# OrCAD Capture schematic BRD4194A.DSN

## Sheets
1 03: I/O Port Connections: size A3; title: EFR32xG27 2.4 GHz 8 dBm Radio Board; rev: A04; company: Silicon Labs; note: BRD4194A
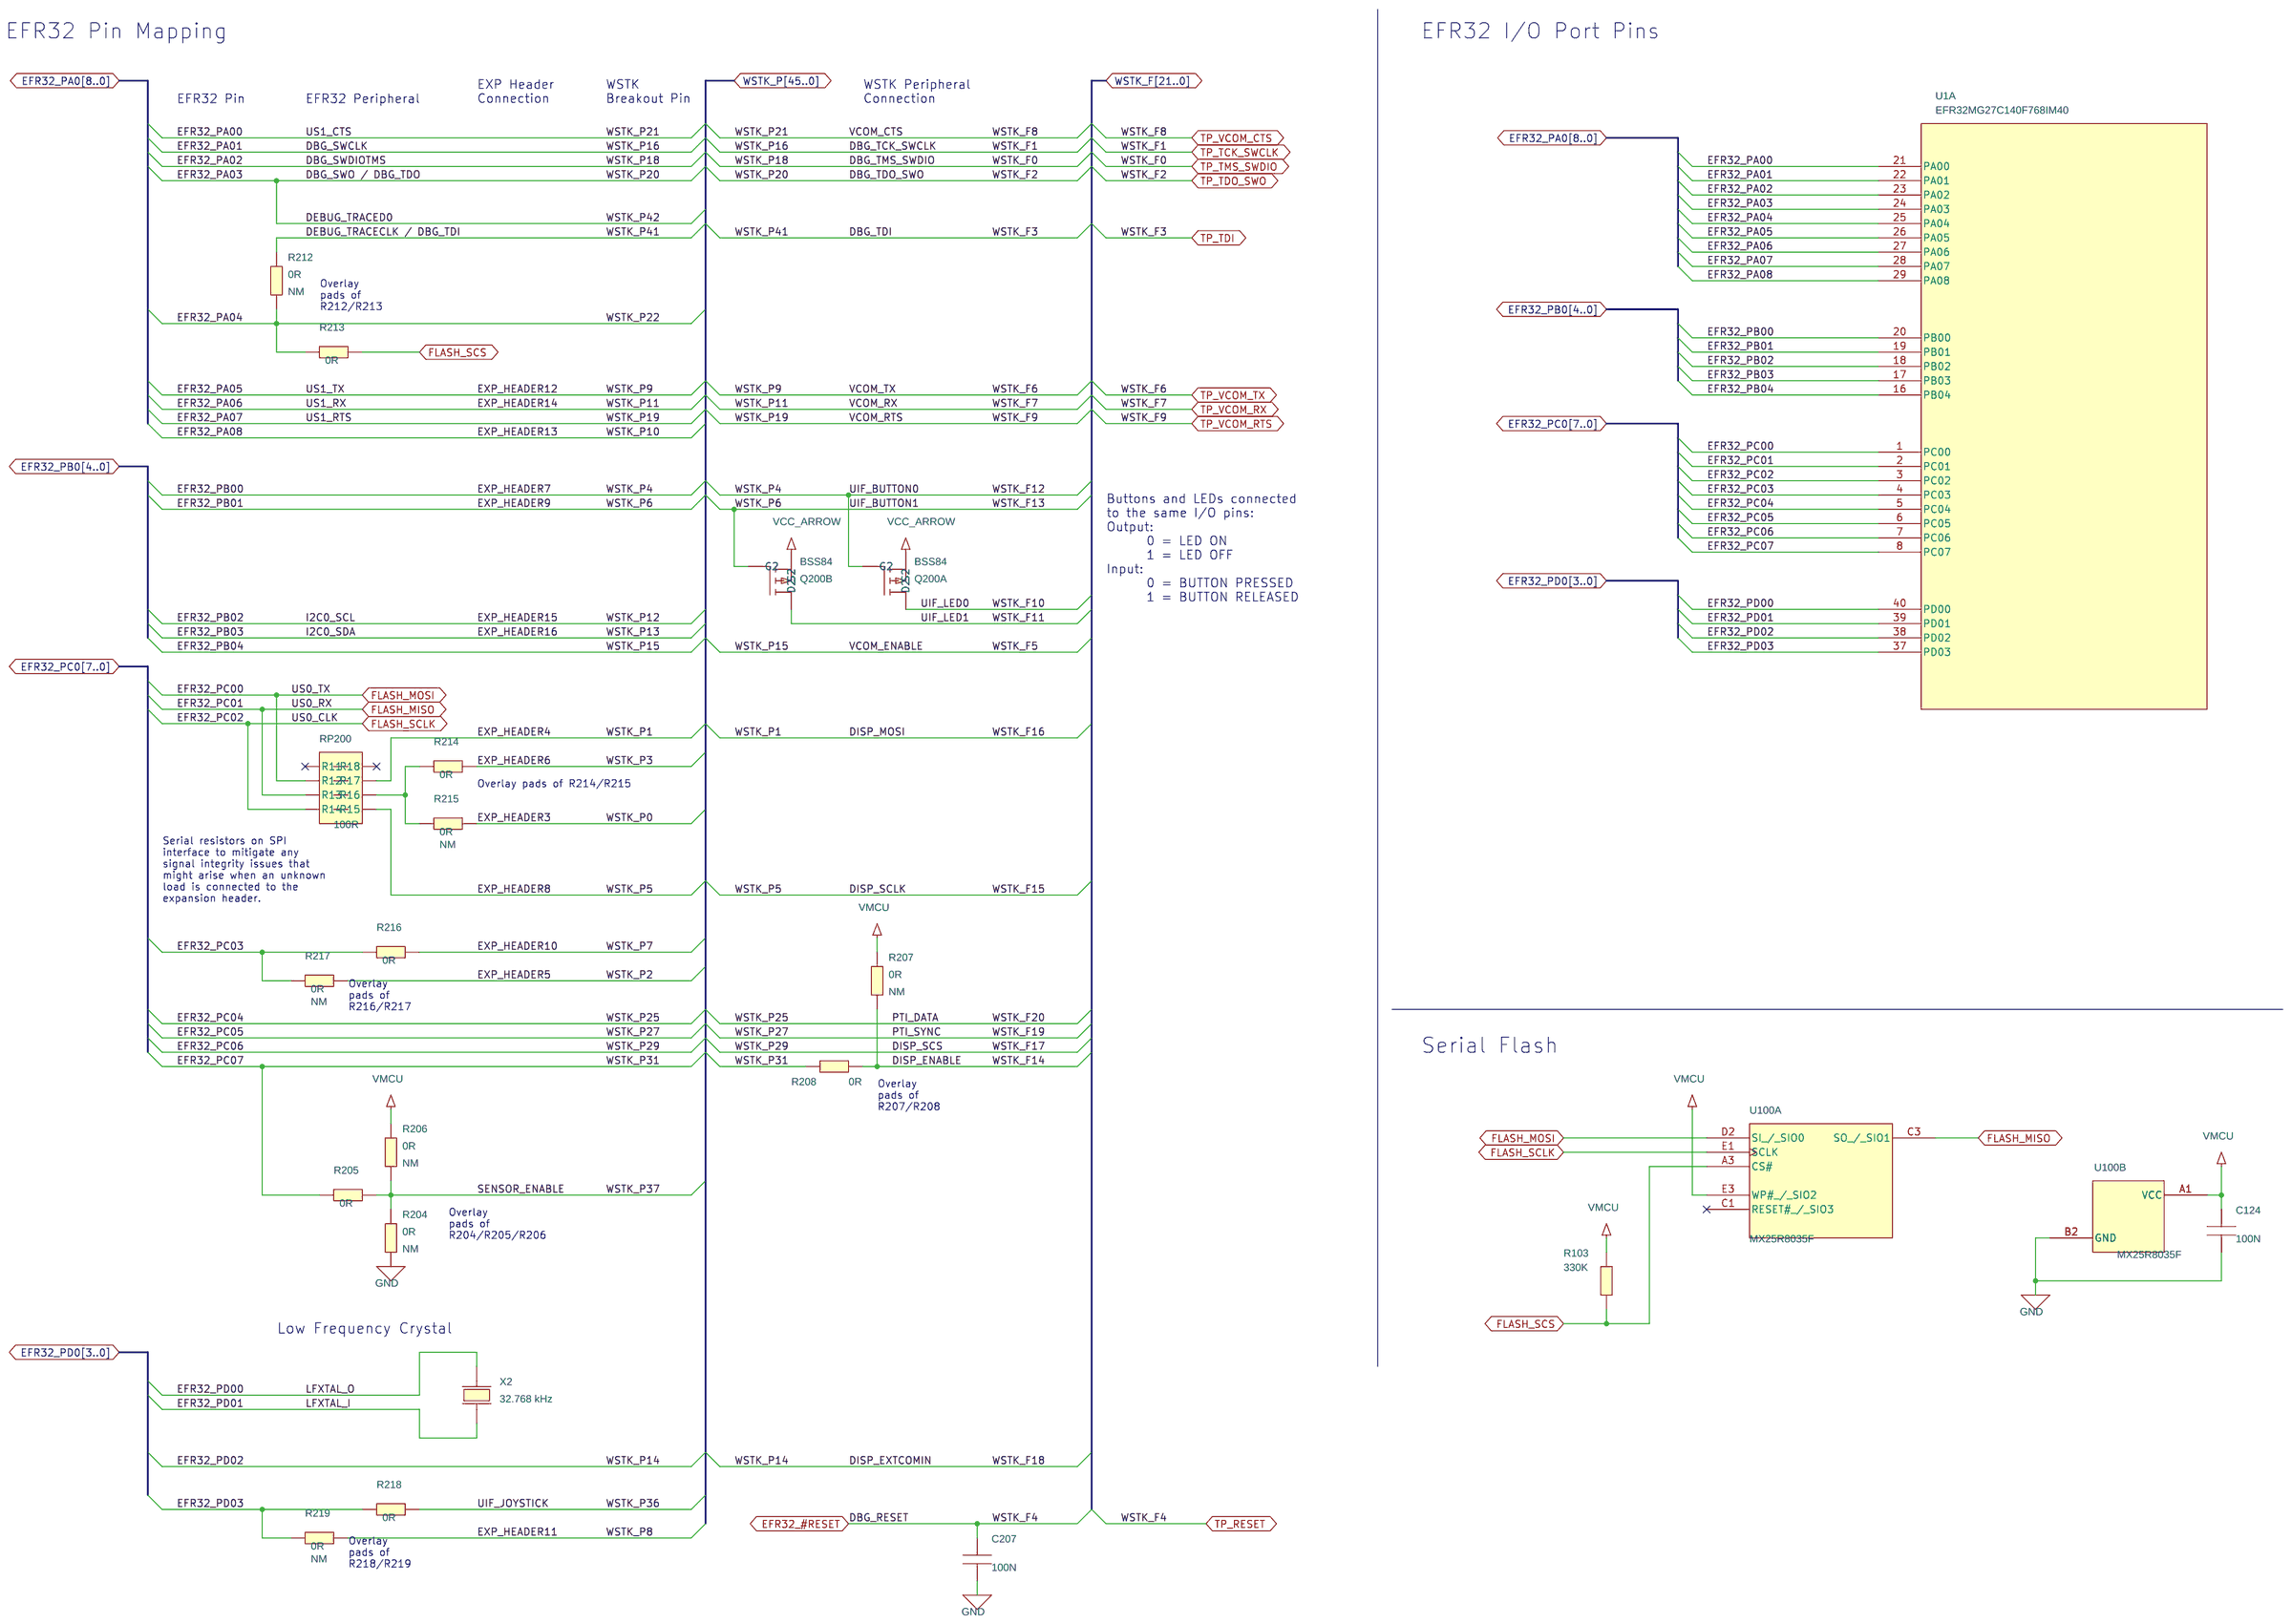
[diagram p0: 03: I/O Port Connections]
2 01: Title Page
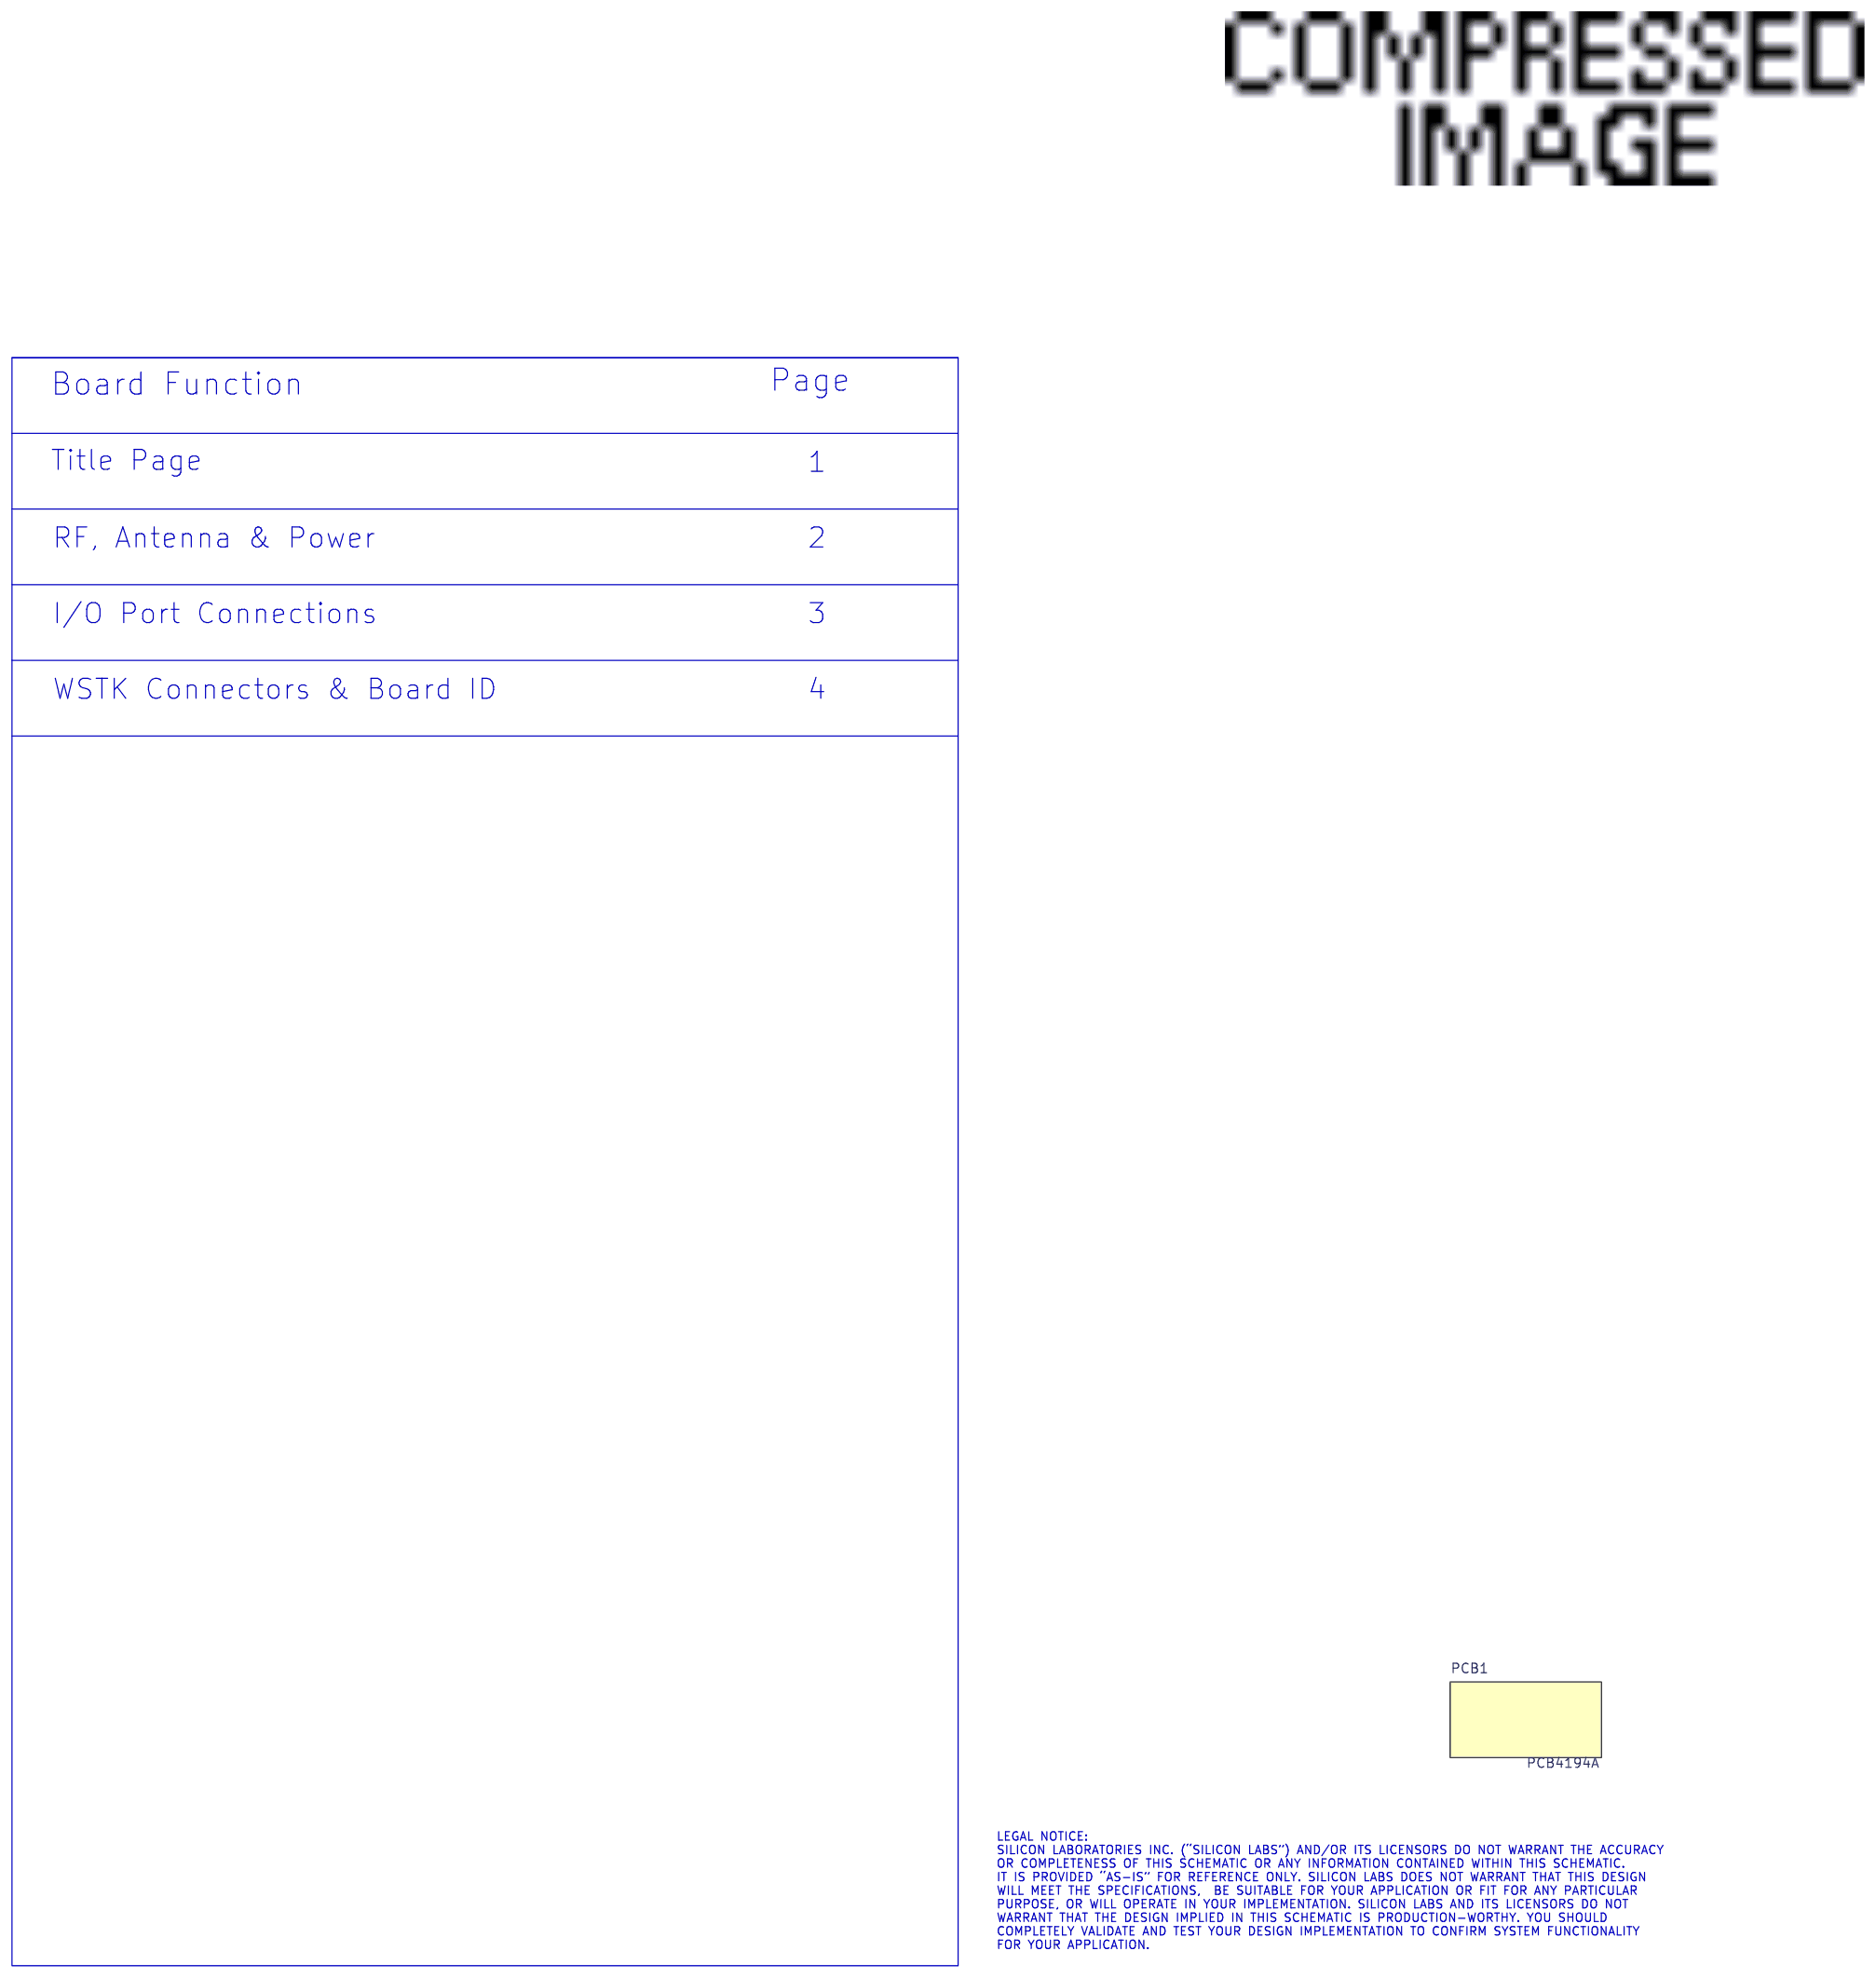
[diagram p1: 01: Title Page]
3 02: RF, Antenna and Power: size A3
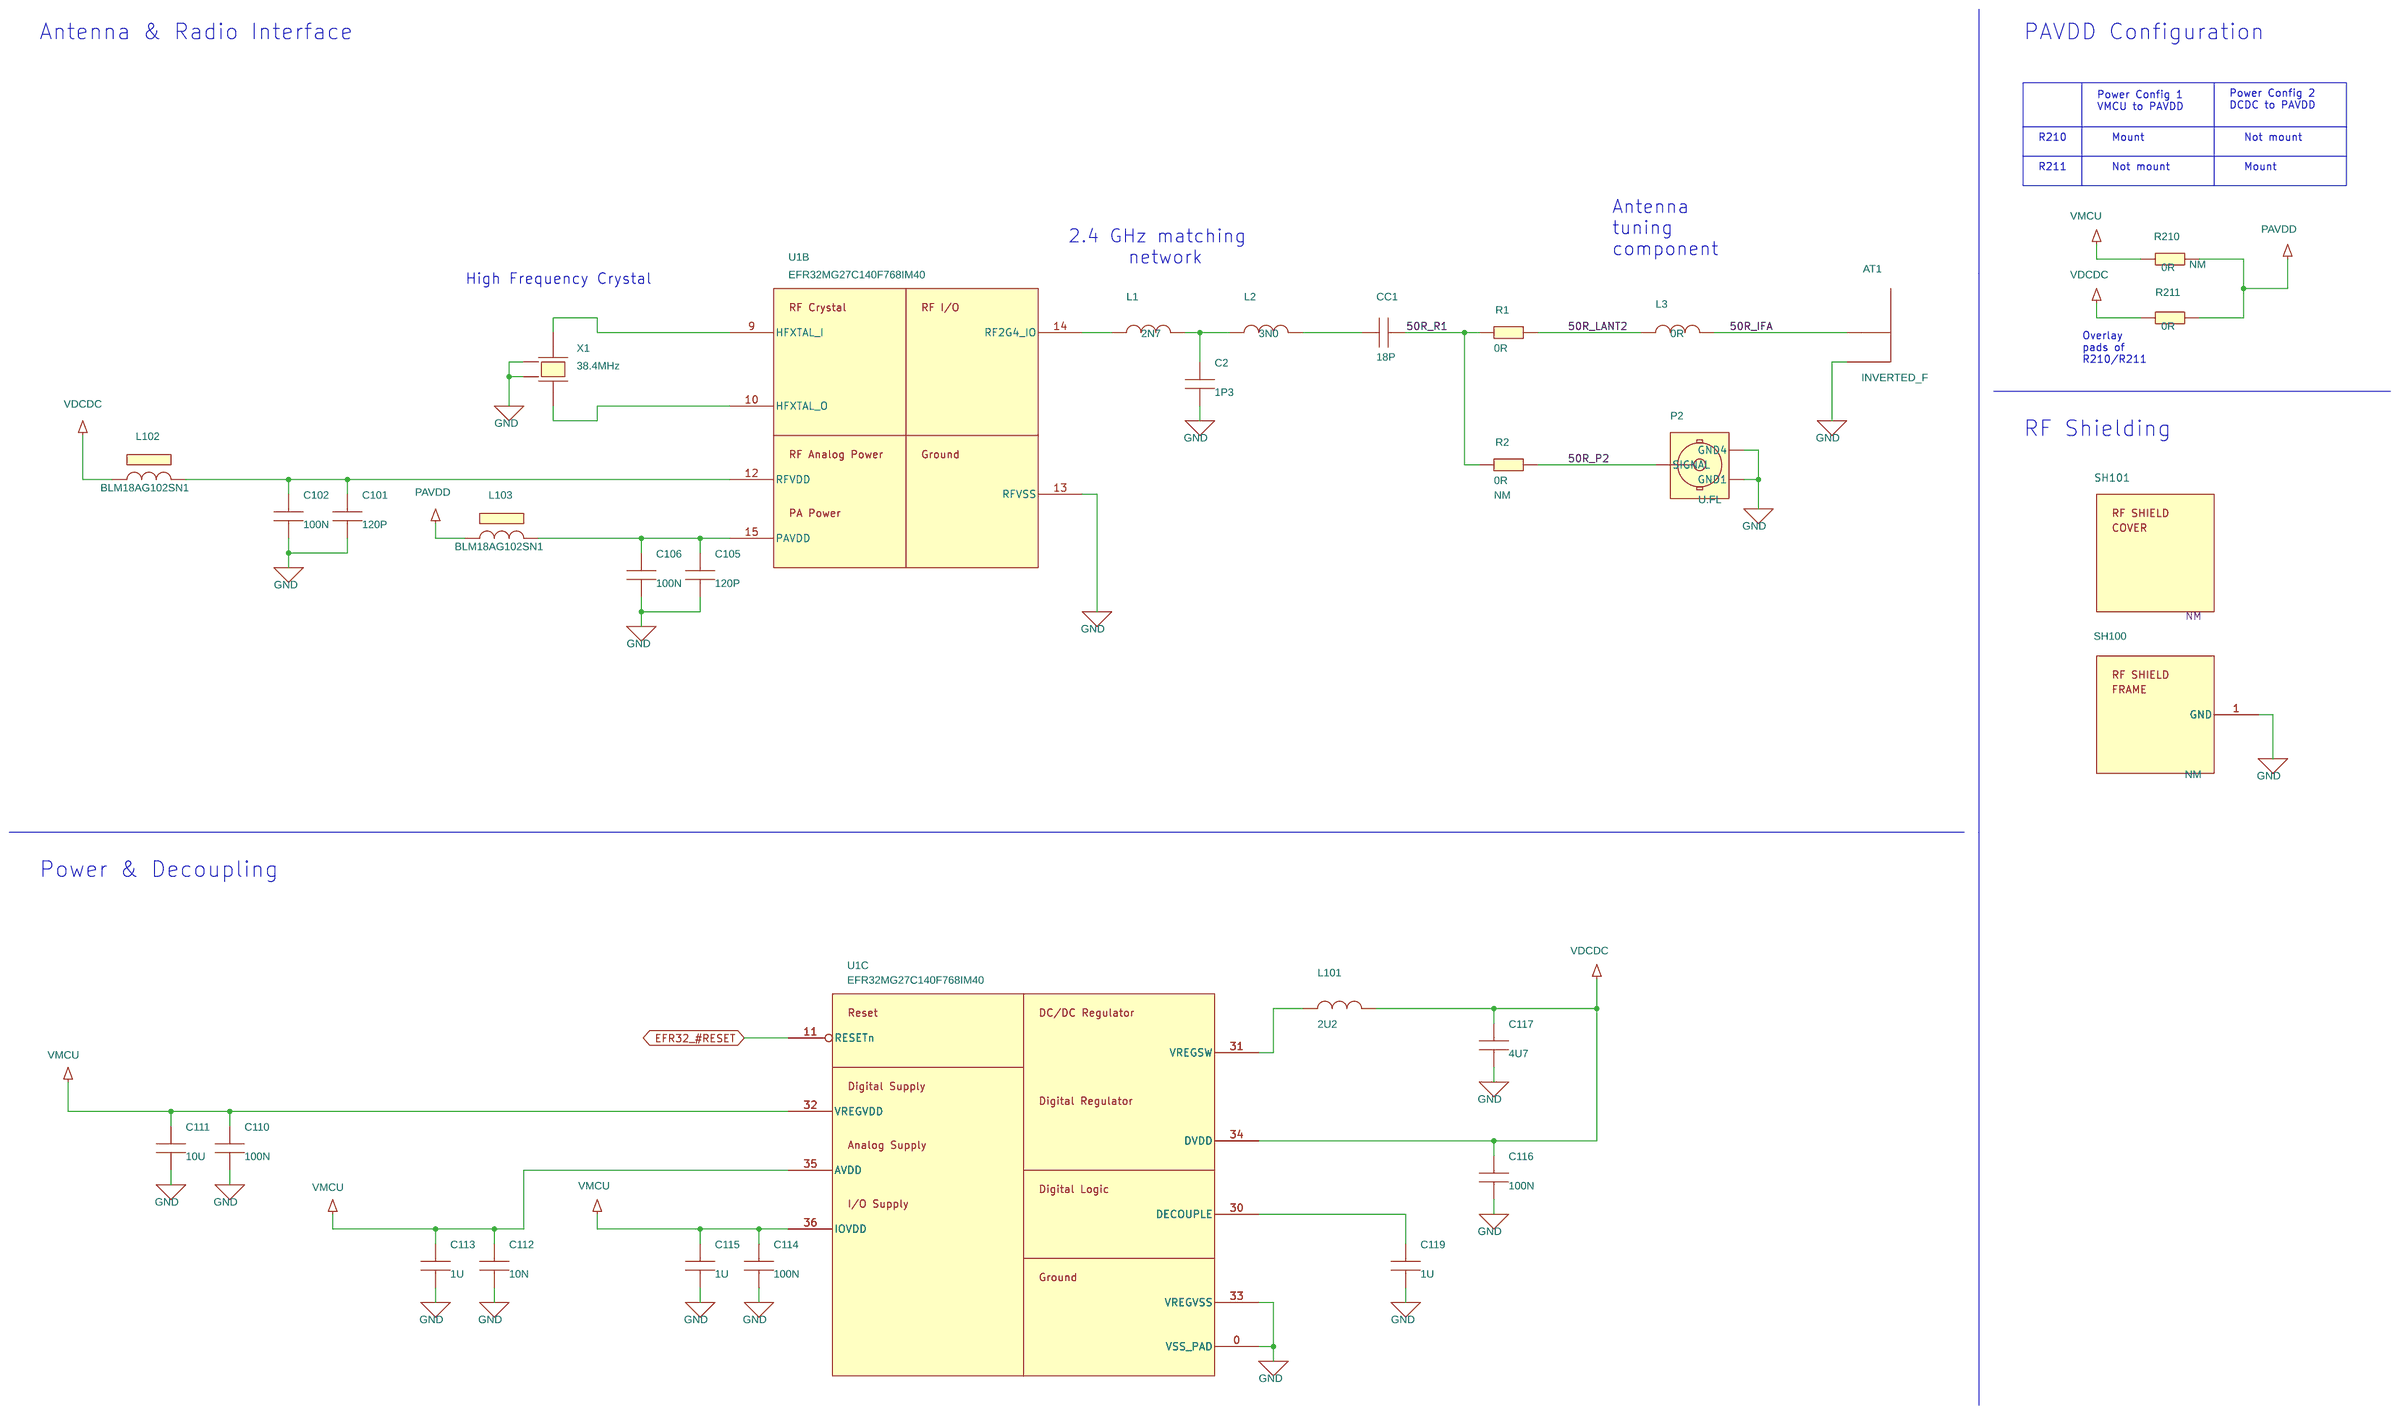
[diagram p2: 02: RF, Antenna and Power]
4 04: WSTK Connectors & Board ID: size A3
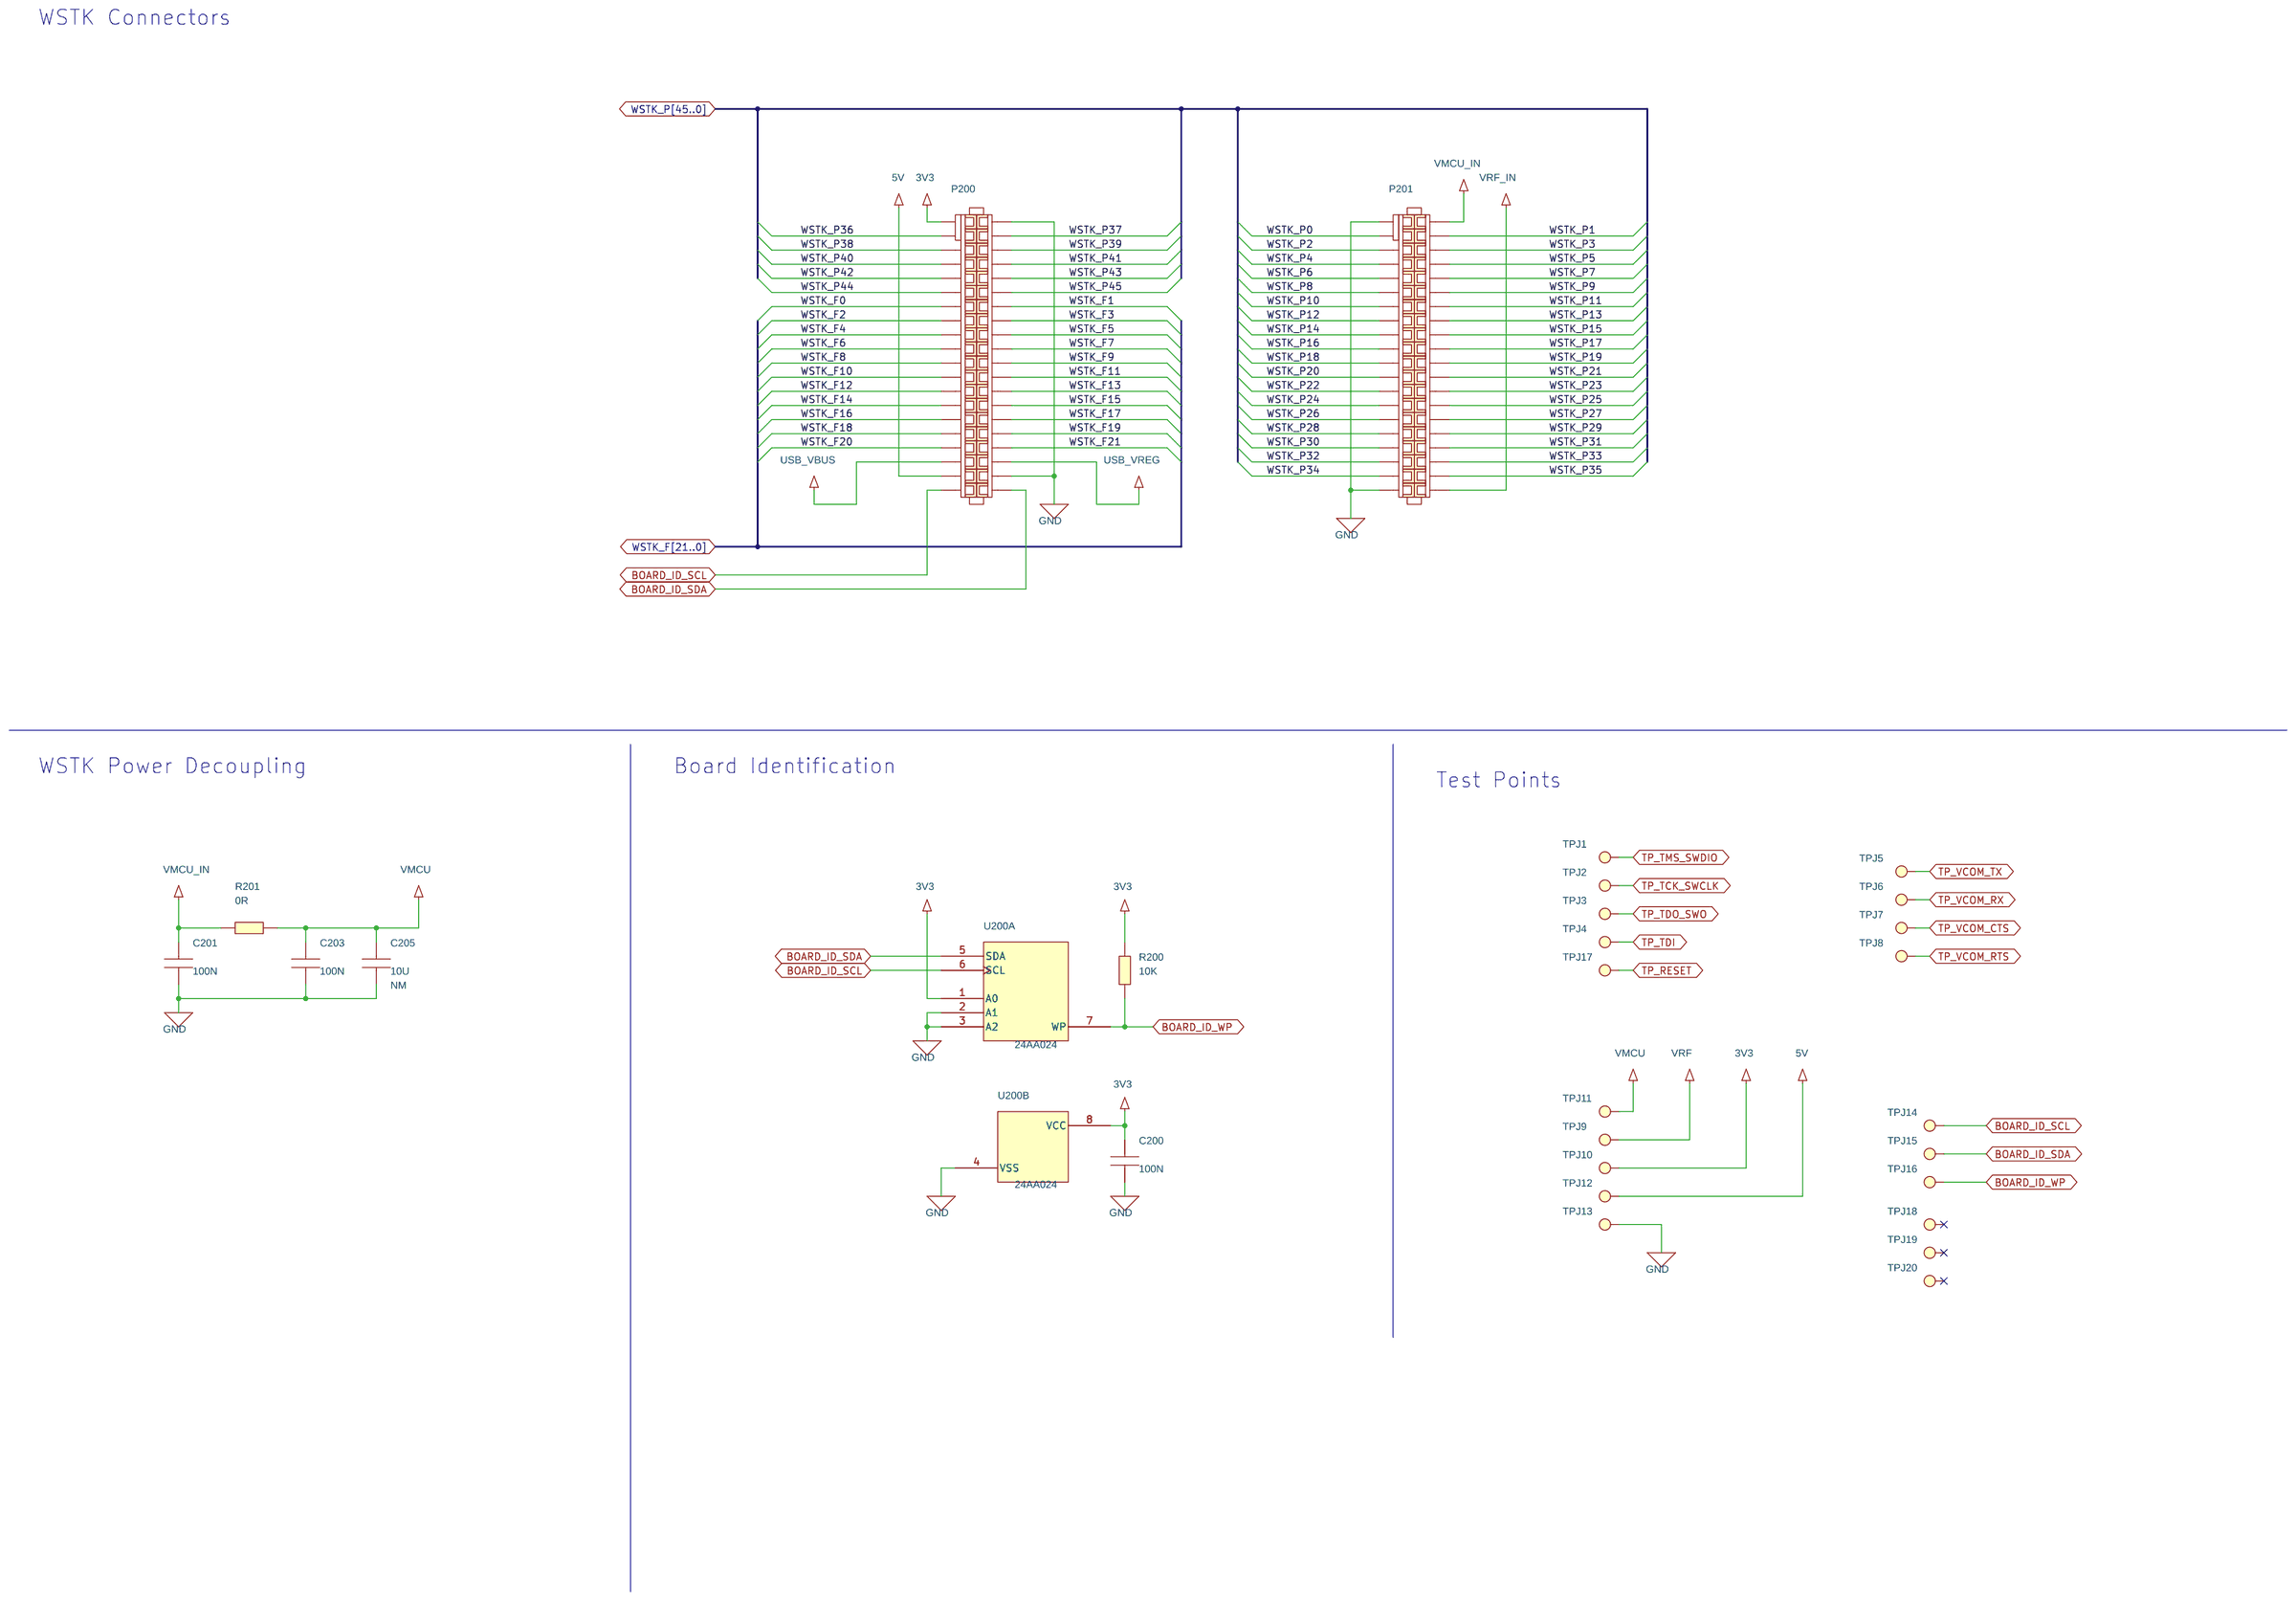
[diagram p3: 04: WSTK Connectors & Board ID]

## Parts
sheet 01: Title Page
PCB1  PCB4194A  [N/A]
sheet 02: RF, Antenna and Power
AT1  INVERTED_F  [EM358x_INVERTED_F]
C2  1P3  [C0201_L]
C101  120P  [C0201_L]
C102  100N  [C0201_L]
C105  120P  [C0201_L]
C106  100N  [C0201_L]
C110  100N  [C0201_L]
C111  10U  [C0603_L]
C112  10N  [C0201_L]
C113  1U  [C0402_L]
C114  100N  [C0201_L]
C115  1U  [C0402_L]
C116  100N  [C0201_L]
C117  4U7  [C0603_L]
C119  1U  [C0201_L]
CC1  18P  [C0201_L]
L1  2N7  [COIL_0201_L]
L2  3N0  [COIL_0201_L]
L3  0R  [COIL_0402_L]
L101  2U2  [COIL_1008_L]
L102  BLM18AG102SN1  [COIL_MUR_BLM18_0603]
L103  BLM18AG102SN1  [COIL_MUR_BLM18_0603]
P2  U.FL  [COAX_HIROSE_U.FL_CL331-0471]
R1  0R  [R0402_L]
R2  0R  [R0402_L]
R210  0R  [R0402_L]
R211  0R  [R0402_L]
SH100  RF_SHIELD_FRAME_BMI-S-202-F  [Laird_BMI-S-202-F]
SH101  RF_SHIELD_COVER_BMI-S-202-C
U1  EFR32MG27C140F768IM40  [QFN40_M040_5.0X5.0_EP_RP_SL]  (sections A,B,C)
X1  38.4MHz  [KDS_DSX211SH_2016]
sheet 03: I/O Port Connections
C124  100N  [C0201_L]
C207  100N  [C0201_L]
Q200  BSS84  [SOT-363]  (sections A,B)
R103  330K  [R0201_L]
R204  0R  [R0402_L]
R205  0R  [R0402_L]
R206  0R  [R0402_L]
R207  0R  [R0402_L]
R208  0R  [R0402_L]
R212  0R  [R0402_L]
R213  0R  [R0402_L]
R214  0R  [R0402_L]
R215  0R  [R0402_L]
R216  0R  [R0402_L]
R217  0R  [R0402_L]
R218  0R  [R0402_L]
R219  0R  [R0402_L]
RP200  100R  [RES_MNR04-8]
U100  MX25R8035F  [BGA8_M040_1.24x1.75_WLCSP]  (sections A,B)
X2  32.768 kHz  [X_MCS_CM8V-T1A]
sheet 04: WSTK Connectors & Board ID
C200  100N  [C0201_L]
C201  100N  [C0201_L]
C203  100N  [C0201_L]
C205  10U  [C0805_L]
P200  SOCKET_WCON_2X20_1.27MM_SMD  [SAM_SFC-120-T2-D-A-2X20_SNUM]
P201  SOCKET_WCON_2X20_1.27MM_SMD  [SAM_SFC-120-T2-D-A-2X20_SNUM]
R200  10K  [R0201_L]
R201  0R  [R0402_L]
TPJ1  TPJ_SMD  [TP_1.0_SMD]
TPJ2  TPJ_SMD  [TP_1.0_SMD]
TPJ3  TPJ_SMD  [TP_1.0_SMD]
TPJ4  TPJ_SMD  [TP_1.0_SMD]
TPJ5  TPJ_SMD  [TP_1.0_SMD]
TPJ6  TPJ_SMD  [TP_1.0_SMD]
TPJ7  TPJ_SMD  [TP_1.0_SMD]
TPJ8  TPJ_SMD  [TP_1.0_SMD]
TPJ9  TPJ_SMD  [TP_1.0_SMD]
TPJ10  TPJ_SMD  [TP_1.0_SMD]
TPJ11  TPJ_SMD  [TP_1.0_SMD]
TPJ12  TPJ_SMD  [TP_1.0_SMD]
TPJ13  TPJ_SMD  [TP_1.0_SMD]
TPJ14  TPJ_SMD  [TP_1.0_SMD]
TPJ15  TPJ_SMD  [TP_1.0_SMD]
TPJ16  TPJ_SMD  [TP_1.0_SMD]
TPJ17  TPJ_SMD  [TP_1.0_SMD]
TPJ18  TPJ_SMD  [TP_1.0_SMD]
TPJ19  TPJ_SMD  [TP_1.0_SMD]
TPJ20  TPJ_SMD  [TP_1.0_SMD]
U200  24AA024  [8-TDFN]  (sections A,B)

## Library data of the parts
PCB1 = PCB: Mfg #: PCB4194A Rev. A00; Price_1K: 1.25
AT1 = INVERTED_F
C2 = C0201: Mfg: Murata; Mfg #: GRM0335C1H1R3WA01D; Technology: C0G; Tolerance: ±0.05P
C101 C105 = C0201: Rating: 50V; Technology: C0G; Tolerance: 5%
C102 C106 C110 C114 C116 C124 C200 C201 C203 C207 = C0201: Rating: 25V; Technology: X5R; Tolerance: 10%
C111 = C0603: Rating: 25V; Technology: X5R; Tolerance: 20%
C112 = C0201: Rating: 10V; Technology: X5R; Tolerance: 10%
C113 C115 = C0402: Rating: 25V; Technology: X5R; Tolerance: 10%
C117 = C0603: Rating: 6.3V; Technology: X5R; Tolerance: 20%
C119 = C0201: Rating: 10V; Technology: X5R; Tolerance: 20%
CC1 = C0201: Mfg: Murata; Mfg #: GJM0335C1E180GB01D; Technology: C0G; Tolerance: ±2%
L1 = L0201: Mfg: Murata; Mfg #: LQP03TN2N7C02D; Tolerance: ±0.2N
L2 = L0201: Mfg: Murata; Mfg #: LQP03TN3N0C02D; Tolerance: ±0.2N
L3 = INDUCTOR
L101 = L1008: Mfg: Samsung; Mfg #: CIG22H2R2MNE; Tolerance: +/-20%
L102 L103 = BLM21B102S
P2 = HIROSE_U.FL: Mfg: KLS; Mfg #: L-KLS1-IPEX-20279-001E-01
R1 R201 = RESISTOR
R2 = RESISTOR: Not Mounted: NM
R204 R206 R207 R210 R212 R215 R217 R219 = R0402: Not Mounted: NM
R205 R208 R211 R213 R214 R216 R218 = R0402
SH100 = RF_SHIELD_FRAME_BMI-S-202-F: Not Mounted: NM
SH101 = RF_SHIELD_COVER_BMI-S-202-C: Not Mounted: NM
U1 = EFR32xG27_QFN40_2G4_BUCK: Mfg #: EFR32MG27C140F768IM40-AR
X1 = DSX211SH: Mfg: Tai-Saw Technology; Mfg #: TZ3398B; Price_1K: 0.512
Q200 = BSS84DW
R103 R200 = R0201
RP200 = MNR04M0APJ101
U100 = MX25R8035
X2 = CM8V-T1A: Mfg: Micro Crystal AG; Mfg #: CM8V-T1A-32.768KHZ-7PF-20PPM-TA-QC
C205 = CAPACITOR: Not Mounted: NM; Technology: X5R
P200 P201 = SOCKET_WCON_2X20_1.27MM_SMD
TPJ1-TPJ20 = TPJ_SMD
U200 = 24AA024: Mfg: Microchip; Mfg #: 24AA024T-I/MNY; Price_1K: 0.26

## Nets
3V3: C200.1 P200.1 R200.2 TPJ10.1(TP) U200.1(A0) U200.8(VCC)
5V: P200.37 TPJ12.1(TP)
GND: AT1.2(GND) C2.2 C101.2 C102.2 C105.2 C106.2 C110.2 C111.2 C112.2 C113.2 C114.2 C115.2 C116.2 C117.2 C119.2 C124.2 C200.2 C201.2 C203.2 C205.2 C207.2 P2.2(GND1) P2.3(GND4) P200.2 P200.38 P201.1 P201.39 R204.2 SH100.1(GND) TPJ13.1(TP) U1.0(VSS_PAD) U1.13(RFVSS) U1.33(VREGVSS) U100.B2(GND) U200.2(A1) U200.3(A2) U200.4(VSS) X1.2 X1.4
50R_IFA: AT1.1(ANT) L3.2
50R_LANT2: L3.1 R1.2
50R_P2: P2.1(SIGNAL) R2.2
50R_R1: CC1.2 R1.1 R2.1
BOARD_ID_SCL: P200.39 TPJ14.1(TP) U200.6(SCL)
BOARD_ID_SDA: P200.40 TPJ15.1(TP) U200.5(SDA)
BOARD_ID_WP: R200.1 TPJ16.1(TP) U200.7(WP)
EFR32_#RESET: C207.1 P200.17 TPJ17.1(TP) U1.11(RESETn)
EFR32_PA00: P200.21 P201.24 TPJ7.1(TP) U1.21(PA00)
EFR32_PA01: P200.14 P201.19 TPJ2.1(TP) U1.22(PA01)
EFR32_PA02: P200.13 P201.21 TPJ1.1(TP) U1.23(PA02)
EFR32_PA03: P200.9 P200.15 P201.23 TPJ3.1(TP) U1.24(PA03)
EFR32_PA04: P201.25 R212.2 R213.1 U1.25(PA04)
EFR32_PA05: P200.19 P201.12 TPJ5.1(TP) U1.26(PA05)
EFR32_PA06: P200.20 P201.14 TPJ6.1(TP) U1.27(PA06)
EFR32_PA07: P200.22 P201.22 TPJ8.1(TP) U1.28(PA07)
EFR32_PA08: P201.13 U1.29(PA08)
EFR32_PB00: P200.25 P201.7 Q200.2(G2) U1.20(PB00)
EFR32_PB01: P200.26 P201.9 Q200.5(G2) U1.19(PB01)
EFR32_PB02: P201.15 U1.18(PB02)
EFR32_PB03: P201.16 U1.17(PB03)
EFR32_PB04: P200.18 P201.18 U1.16(PB04)
EFR32_PC00: RP200.2(R12) U1.1(PC00) U100.D2(SI_/_SIO0)
EFR32_PC01: RP200.3(R13) U1.2(PC01) U100.C3(SO_/_SIO1)
EFR32_PC02: RP200.4(R14) U1.3(PC02) U100.E1(SCLK)
EFR32_PC03: R216.1 R217.1 U1.4(PC03)
EFR32_PC04: P200.33 P201.28 U1.5(PC04)
EFR32_PC05: P200.32 P201.30 U1.6(PC05)
EFR32_PC06: P200.30 P201.32 U1.7(PC06)
EFR32_PC07: P201.34 R205.1 R208.1 U1.8(PC07)
EFR32_PD00: U1.40(PD00) X2.1
EFR32_PD01: U1.39(PD01) X2.2
EFR32_PD02: P200.31 P201.17 U1.38(PD02)
EFR32_PD03: R218.1 R219.1 U1.37(PD03)
FLASH_SCS: R103.1 R213.2 U100.A3(CS#)
PAVDD: L103.1 R210.1 R211.2
TP_TDI: P200.8 P200.16 R212.1 TPJ4.1(TP)
USB_VBUS: P200.35
USB_VREG: P200.36
VDCDC: C116.1 C117.1 L101.2 L102.1 R211.1 U1.34(DVDD)
VMCU: C110.1 C111.1 C112.1 C113.1 C114.1 C115.1 C124.1 C203.1 C205.1 Q200.1(S2) Q200.4(S2) R103.2 R201.2 R206.1 R207.1 R210.2 TPJ11.1(TP) U1.32(VREGVDD) U1.35(AVDD) U1.36(IOVDD) U100.A1(VCC) U100.E3(WP#_/_SIO2)
VMCU_IN: C201.1 P201.2 R201.1
VRF: TPJ9.1(TP)
VRF_IN: P201.40
WSTK_F10: P200.23 Q200.6(D2)
WSTK_F11: P200.24 Q200.3(D2)
WSTK_F14: P200.27 R207.2 R208.2
WSTK_F15: P200.28 P201.8 RP200.5(R15)
WSTK_F16: P200.29 P201.4 RP200.7(R17)
WSTK_F21: P200.34
WSTK_P0: P201.3 R215.2
WSTK_P2: P201.5 R217.2
WSTK_P3: P201.6 R214.2
WSTK_P7: P201.10 R216.2
WSTK_P8: P201.11 R219.2
WSTK_P17: P201.20
WSTK_P23: P201.26
WSTK_P24: P201.27
WSTK_P26: P201.29
WSTK_P28: P201.31
WSTK_P30: P201.33
WSTK_P32: P201.35
WSTK_P33: P201.36
WSTK_P34: P201.37
WSTK_P35: P201.38
WSTK_P36: P200.3 R218.2
WSTK_P37: P200.4 R204.1 R205.2 R206.2
WSTK_P38: P200.5
WSTK_P39: P200.6
WSTK_P40: P200.7
WSTK_P43: P200.10
WSTK_P44: P200.11
WSTK_P45: P200.12
N16773989: U1.9(HFXTAL_I) X1.3
N16774051: U1.10(HFXTAL_O) X1.1
N16774211: C101.1 C102.1 L102.2 U1.12(RFVDD)
N16774267: C105.1 C106.1 L103.2 U1.15(PAVDD)
N16774345: L1.1 U1.14(RF2G4_IO)
N16774387: C2.1 L1.2 L2.1
N16775186: L101.1 U1.31(VREGSW)
N16775238: C119.1 U1.30(DECOUPLE)
N16778861: R214.1 R215.1 RP200.6(R16)
N16787268: CC1.1 L2.2

Not connected (* = marked no-connect by the designer): RP200 1(R11)* 8(R18)*; TPJ18 1(TP)*; TPJ19 1(TP)*; TPJ20 1(TP)*; U100 C1(RESET#_/_SIO3)*

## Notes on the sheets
sheet 1
- EFR32 Pin Mapping
- EFR32 I/O Port Pins
- EXP Header
  Connection
- WSTK
  Breakout Pin
- WSTK Peripheral
  Connection
- EFR32 Pin
- EFR32 Peripheral
- Overlay
  pads of
  R212/R213
- Buttons and LEDs connected
  to the same I/O pins:
  Output:
        0 = LED ON
        1 = LED OFF
  Input:
        0 = BUTTON PRESSED
        1 = BUTTON RELEASED
- Overlay pads of R214/R215
- Serial resistors on SPI
  interface to mitigate any
  signal integrity issues that
  might arise when an unknown
  load is connected to the
  expansion header.
- Overlay
  pads of
  R216/R217
- Serial Flash
- Overlay
  pads of
  R207/R208
- Overlay
  pads of
  R204/R205/R206
- Low Frequency Crystal
- Overlay
  pads of
  R218/R219
sheet 2
- Board Function
- Page
- Title Page
- 1
- RF, Antenna & Power
- 2
- I/O Port Connections
- 3
- WSTK Connectors & Board ID
- 4
- LEGAL NOTICE:
  SILICON LABORATORIES INC. (“SILICON LABS”) AND/OR ITS LICENSORS DO NOT WARRANT THE ACCURACY
  OR COMPLETENESS OF THIS SCHEMATIC OR ANY INFORMATION CONTAINED WITHIN THIS SCHEMATIC.
  IT IS PROVIDED “AS-IS” FOR REFERENCE ONLY. SILICON LABS DOES NOT WARRANT THAT THIS DESIGN
  WILL MEET THE SPECIFICATIONS,  BE SUITABLE FOR YOUR APPLICATION OR FIT FOR ANY PARTICULAR
  PURPOSE, OR WILL OPERATE IN YOUR IMPLEMENTATION. SILICON LABS AND ITS LICENSORS DO NOT
  WARRANT THAT THE DESIGN IMPLIED IN THIS SCHEMATIC IS PRODUCTION-WORTHY. YOU SHOULD
  COMPLETELY VALIDATE AND TEST YOUR DESIGN IMPLEMENTATION TO CONFIRM SYSTEM FUNCTIONALITY
  FOR YOUR APPLICATION.
sheet 3
- Antenna & Radio Interface
- PAVDD Configuration
- Power Config 1
  VMCU to PAVDD
- Power Config 2
  DCDC to PAVDD
- R210
- Mount
- Not mount
- R211
- Not mount
- Mount
- Antenna
  tuning
  component
- 2.4 GHz matching
        network
- High Frequency Crystal
- Overlay
  pads of
  R210/R211
- RF Shielding
- Power & Decoupling
sheet 4
- WSTK Connectors
- WSTK Power Decoupling
- Board Identification
- Test Points
